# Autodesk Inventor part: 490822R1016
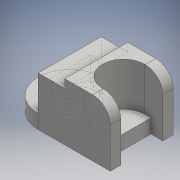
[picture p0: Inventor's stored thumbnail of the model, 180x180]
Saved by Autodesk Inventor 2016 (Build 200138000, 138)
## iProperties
Created: 2019-08
Part Number: 490822R1016
Material: 일반
Document SubType Name: Modeling
Designer: EDU-1-15
Density: 1 g/cm^3
Appearance: 기본값
Author: EDU-1-15
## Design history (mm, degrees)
sketch "스케치2"
  geometry: L1 (0, 45)-(77, 45); L2 (0, -45)-(77, -45); L3 (77, -45)-(103, -45); L4 (77, 45)-(103, 45); L5 (103, 45)-(103, 30); L6 (103, -45)-(103, -30); L7 (103, -30)-(77, -30); L8 (77, 30)-(103, 30); A1 r 45 centre (0, 0) between (0, 45) and (0, -45); A2 r 30 centre (77, 0) between (77, 30) and (77, -30); 1 further point
  constraints: 16 end point, 5 horizontal, 4 point on circle, 2 centre point, 2 vertical, 1 coincident
  dimensions: "d0" = 90 diameter of A1; "d2" = 77 distance of L1.start L1.end; "d3" = 26 distance of L2.end L3.end; "d4" = 15 distance of L4.end L5.end; "d5" = 15 distance of L3.end L6.end; "d6" = 26 distance of L6.end L7.end; "d7" = 30 radius of A2
extrude "돌출1" new body sketch "스케치2" distance "d8" = 20; taper "d9" = 0 deg
sketch "스케치4"
  geometry: L1 (45, 20)-(45, 0) reference; L2 (45, 0)-(-47, 0) reference; L3 (-47, 0)-(-47, 20) reference; L4 (-47, 20)-(45, 20) reference; L5 (0, 0)-(0, 20) reference; L6 (0, 20)-(0, 70); L7 (0, 70)-(-38, 70); L8 (-38, 70)-(-38, 82); L9 (-103, 0)-(-103, 20) reference; L10 (-77, 20)-(-103, 20) reference; L11 (-103, 20)-(-103, 82); L12 (-103, 82)-(-38, 82); L13 (-77, 20)-(-47, 20) reference; L14 (-103, 20)-(0, 20) reference; L15 (0, 20)-(-103, 20)
  constraints: 12 end point, 3 perpendicular, 2 vertical, 1 collinear
  dimensions: "d10" = 50 distance of L5.end L6.end; "d11" = 38 distance of L6.end L7.end; "d12" = 12 distance of L7.end L8.end
extrude "돌출2" join sketch "스케치4" stored distance "d13" = 90; taper "d14" = 0 deg
sketch "스케치5"
  geometry: L1 (0, 0)-(26, 0) reference; L2 (26, 60)-(0, 60) reference; L3 (0, 0)-(0, 60) reference; A1 r 30 centre (26, 30) between (26, 0) and (26, 60) reference; 1 further point
extrude "돌출3" cut sketch "스케치5" stored distance "d15" = 90; taper "d16" = 0 deg
sketch "스케치6"
  geometry: C1 r 11 at (0, 0); 1 further point
  constraints: 1 centre point, 1 coincident
  dimensions: "d17" = 22 diameter of C1
extrude "돌출4" cut sketch "스케치6" distance "d18" = 20; taper "d19" = 0 deg
node "작업 평면1"
sketch "스케치8"
  geometry: L1 (0, -30)-(0, 30); A1 r 30 centre (0, 0) between (0, -30) and (0, 30); 1 further point
  constraints: 2 end point, 2 point on circle, 1 centre point, 1 coincident, 1 vertical
  dimensions: "d24" = 60 diameter of A1
extrude "돌출6" cut sketch "스케치8" distance "d25" = 35; taper "d26" = 0 deg
sketch "스케치9"
  geometry: L1 (77, 30)-(103, 30) reference; L2 (103, 30)-(103, 45) reference; L3 (38, 45)-(103, 45) reference; L4 (103, -30)-(77, -30) reference; L5 (103, -45)-(103, -30) reference; L6 (103, -45)-(38, -45) reference; L7 (86, 30)-(86, -30); A1 r 30 centre (77, 0) between (77, 30) and (77, -30) reference; 1 further point
  constraints: 2 end point, 2 point on line, 1 perpendicular
  dimensions: "d27" = 17 distance between parallel lines of L2 L7
extrude "돌출7" join sketch "스케치9" distance "d28" = 20; taper "d29" = 0 deg
fillet "모깎기1" dims "d30" = 25
node "솔리드1"
node "투영된 루프1"
node "절단 모서리 투영1"
